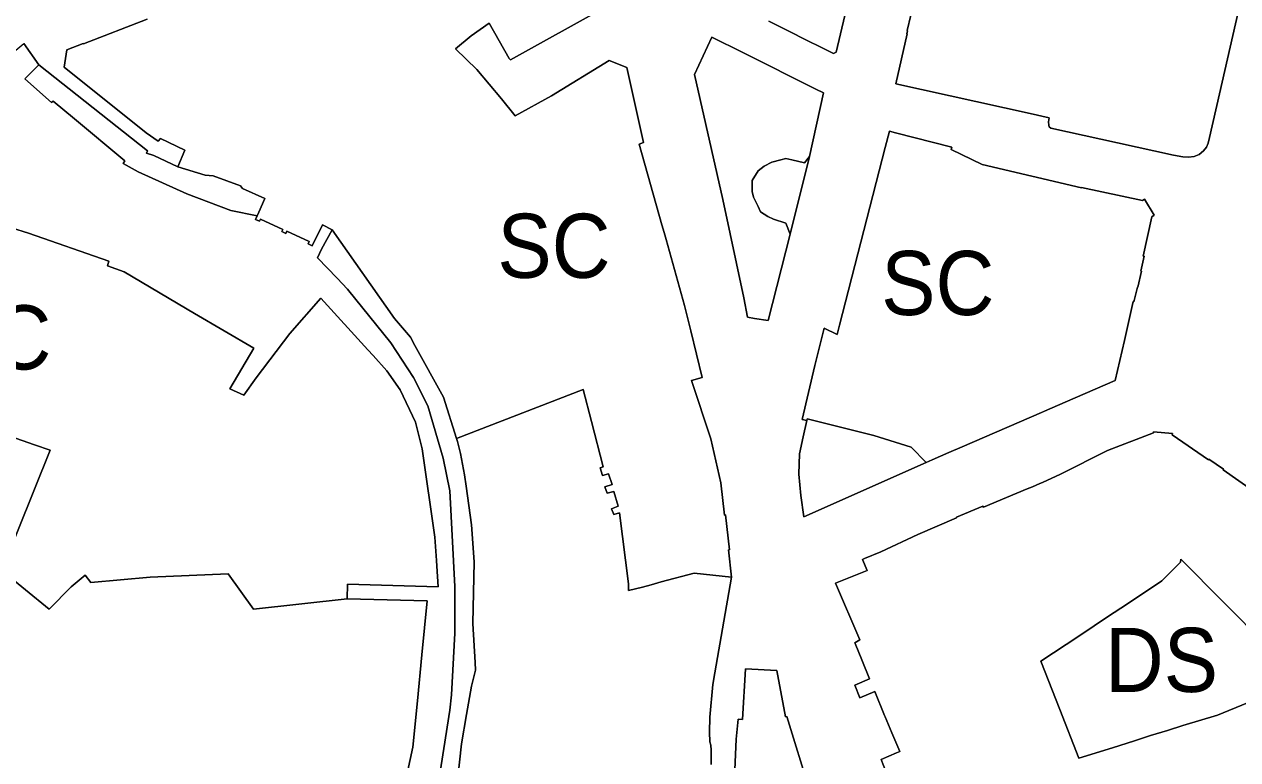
# Model space of a CAD drawing. Extents: x -650451 to -642268, y -1075216 to -1066610.
# Drawn here: x -647095.1 to -646868, y -1070849.7 to -1070712 of the extents above; entities that cross this region are included whole.
import ezdxf

# ---------------------------------------------------------------- set-up
doc = ezdxf.new("R2010")
doc.units = 0
doc.header["$LTSCALE"] = 4.8
for name, color, linetype, lineweight in [('1', 7, 'Continuous', 13), ('11', 7, 'Continuous', 13), ('15', 7, 'Continuous', 13), ('17', 7, 'Continuous', 13), ('2', 7, 'Continuous', 13), ('24', 7, 'Continuous', 13), ('40', 7, 'Continuous', 13), ('45', 7, 'Continuous', 13)]:
    doc.layers.add(name, color=color, linetype=linetype, lineweight=lineweight)
doc.layers.add('62', color=7, linetype='Continuous')

msp = doc.modelspace()

# ---------------------------------------------------------------- linework, layer by layer
at = {"layer": '1'}
msp.add_lwpolyline([(-646933.37, -1070853.01), (-646934.73, -1070849.64), (-646931.81, -1070848.41), (-646931.22, -1070848.17), (-646932.72, -1070844.62), (-646933.96, -1070841.66), (-646934.02, -1070841.52), (-646934.07, -1070841.39), (-646935.9, -1070836.93), (-646938.71, -1070838.08), (-646939.64, -1070835.71), (-646936.86, -1070834.57), (-646938.33, -1070831), (-646939.58, -1070827.93), (-646939.64, -1070827.79), (-646938.71, -1070827.23), (-646943.25, -1070816.65), (-646937.34, -1070814.25), (-646938.18, -1070812.2), (-646937.8, -1070812.01), (-646934.79, -1070810.78), (-646927.81, -1070807.55), (-646920.6, -1070804.42), (-646920.63, -1070804.31), (-646915.65, -1070802.21), (-646915.57, -1070802.42), (-646911.24, -1070800.61), (-646907.38, -1070798.99), (-646906.41, -1070798.59), (-646904.98, -1070797.99), (-646904.51, -1070797.79), (-646901.12, -1070796.23), (-646892.37, -1070791.83), (-646883.74, -1070788.5), (-646883.73, -1070788.3), (-646880.19, -1070788.64), (-646880.23, -1070788.85), (-646873.47, -1070793.54), (-646873.38, -1070793.42), (-646870.63, -1070795.33), (-646870.72, -1070795.45), (-646864.19, -1070799.98)], dxfattribs=at)
msp.add_lwpolyline([(-646878.61, -1070812.14), (-646878.66, -1070812.72), (-646882.18, -1070816.21), (-646887.3, -1070819.61), (-646889.85, -1070821.3), (-646892.34, -1070822.96), (-646897.34, -1070826.28), (-646900.09, -1070828.1), (-646904.8, -1070831.23), (-646901.26, -1070840.31), (-646897.71, -1070849.39), (-646891.42, -1070847.44), (-646887.32, -1070846.14), (-646884.27, -1070845.17), (-646881.11, -1070844.21), (-646878.26, -1070843.29), (-646871.78, -1070841.33), (-646860.55, -1070836.71), (-646856.41, -1070834.13), (-646862.56, -1070828.29)], close=True, dxfattribs=at)
at = {"layer": '11'}
for points in [[(-646935.85, -1070686.31), (-646943.1, -1070717.25), (-646943.61, -1070717.52), (-646945, -1070716.82), (-646949.56, -1070714.54), (-646951.12, -1070713.75), (-646955.71, -1070711.45)], [(-647127.36, -1070780.55), (-647112.25, -1070785.78), (-647100.16, -1070788.3), (-647093.12, -1070790.76), (-647090.24, -1070791.73), (-647099.26, -1070814.25)]]:
    msp.add_lwpolyline(points, dxfattribs=at)
msp.add_lwpolyline([(-646951.73, -1070751.34), (-646952.54, -1070749.28), (-646954.87, -1070748.5), (-646955.91, -1070747.98), (-646957.27, -1070747.14), (-646957.74, -1070746.13), (-646958.58, -1070744.41), (-646958.82, -1070743.34), (-646958.83, -1070741.26), (-646957.75, -1070739.44), (-646956.58, -1070738.61), (-646955.14, -1070737.86), (-646953.5, -1070737.42), (-646952.53, -1070737.15), (-646951.45, -1070737.4), (-646949.04, -1070737.98), (-646948.12, -1070736.75)], close=True, dxfattribs=at)
at = {"layer": '15'}
msp.add_line((-646951.73, -1070751.34), (-646948.12, -1070736.75), dxfattribs=at)
for points in [[(-646955.71, -1070711.45), (-646951.12, -1070713.75), (-646949.56, -1070714.54), (-646945, -1070716.82), (-646943.61, -1070717.52), (-646943.1, -1070717.25), (-646935.85, -1070686.31)], [(-646929.18, -1070710.3), (-646929.85, -1070713.22), (-646929.76, -1070713.24), (-646929.89, -1070713.79), (-646929.81, -1070713.81), (-646931.96, -1070723.16), (-646906.84, -1070728.72), (-646903.24, -1070729.57), (-646903.4, -1070730.32), (-646903.35, -1070730.9), (-646903.24, -1070731.23), (-646902.96, -1070731.45), (-646890.48, -1070734.21), (-646880.01, -1070736.53), (-646878.25, -1070736.85), (-646877.21, -1070736.9), (-646876.15, -1070736.76), (-646875.17, -1070736.39), (-646874.38, -1070735.72), (-646873.8, -1070735.04), (-646873.49, -1070734.28), (-646873.25, -1070733.21), (-646871.4, -1070725.07), (-646865.92, -1070700.98)], [(-646962.68, -1070815.49), (-646963.26, -1070810.4), (-646963.1, -1070810.38), (-646963.84, -1070803.87), (-646963.99, -1070803.89), (-646964.71, -1070797.83), (-646966.6, -1070789.62), (-646970.21, -1070778.7), (-646968.19, -1070778.16), (-646970.32, -1070769.4), (-646971.48, -1070764.65), (-646974.94, -1070752.34), (-646975.32, -1070751.02), (-646975.74, -1070749.55), (-646980.02, -1070734.49), (-646979.18, -1070734.14), (-646982.32, -1070720.12), (-646985.62, -1070718.8), (-646996.42, -1070725.42), (-647003.21, -1070729.14), (-647005.76, -1070725.98), (-647010.36, -1070720.51), (-647014.36, -1070716.64), (-647011.4, -1070714.21), (-647008.07, -1070711.83), (-647004.34, -1070718.44), (-647004.1, -1070718.67), (-646985.98, -1070708.66)], [(-647072.09, -1070711.08), (-647084.01, -1070715.68), (-647084.02, -1070715.63), (-647087.09, -1070716.82), (-647087.57, -1070720.08), (-647072.24, -1070732.33), (-647069.98, -1070733.93), (-647069.6, -1070733.43), (-647065.03, -1070735.57), (-647066.34, -1070738.73)], [(-646948.12, -1070736.75), (-646945.51, -1070724.86), (-646946.94, -1070724.15), (-646948.32, -1070723.46), (-646952.89, -1070721.18), (-646954.46, -1070720.4), (-646960.62, -1070717.32), (-646966.41, -1070714.43), (-646969.61, -1070721.45), (-646964.33, -1070744.8), (-646960.41, -1070763.23), (-646959.73, -1070766.88), (-646958.42, -1070767.08), (-646955.83, -1070767.49), (-646951.73, -1070751.34)], [(-647099.98, -1070715.28), (-647098.12, -1070718.12), (-647095.14, -1070715.62), (-647092.33, -1070719.64)], [(-647066.34, -1070738.73), (-647070.79, -1070736.62), (-647072.18, -1070736.18), (-647071.99, -1070735.71), (-647092.33, -1070719.64), (-647095.14, -1070715.62)], [(-647092.33, -1070719.64), (-647094.99, -1070722.25), (-647089.94, -1070726.7), (-647089.63, -1070726.41), (-647085.69, -1070729.7), (-647076.27, -1070737.56), (-647076.58, -1070738.1), (-647073.76, -1070739.62), (-647064.65, -1070743.79), (-647056.4, -1070746.9), (-647051.47, -1070747.87)], [(-646926.29, -1070794.08), (-646925.14, -1070793.57), (-646922.03, -1070792.21), (-646919.55, -1070791.13), (-646904.69, -1070784.68), (-646904.14, -1070784.44), (-646900.24, -1070782.75), (-646890.91, -1070778.69), (-646889.19, -1070771.22), (-646887.53, -1070763.95), (-646887.39, -1070763.96), (-646886.76, -1070761.25), (-646886.64, -1070761.25), (-646885.96, -1070758.23), (-646886.1, -1070758.22), (-646885.5, -1070755.44), (-646885.65, -1070755.43), (-646884.03, -1070748.05), (-646883.59, -1070747.76), (-646885.4, -1070744.75), (-646885.82, -1070744.99), (-646897.21, -1070742.56), (-646897.22, -1070742.62), (-646915.78, -1070738.26), (-646921.6, -1070735.48), (-646921.48, -1070735.03), (-646932, -1070732.32), (-646933.16, -1070732.02), (-646933.96, -1070735.12), (-646942.5, -1070768.36), (-646942.95, -1070770.09), (-646945.36, -1070768.9), (-646947.09, -1070775.88), (-646949.48, -1070785.99), (-646948.64, -1070786.2)], [(-647051.47, -1070747.87), (-647051.77, -1070748.55), (-647051.06, -1070748.88), (-647050.87, -1070748.48), (-647046.68, -1070750.42), (-647046.87, -1070750.83), (-647046.12, -1070751.18), (-647045.93, -1070750.77), (-647041.73, -1070752.72), (-647041.92, -1070753.13), (-647041.16, -1070753.49), (-647039.26, -1070749.59), (-647037.47, -1070750.49)], [(-647034.61, -1070819.54), (-647034.58, -1070816.84), (-647017.62, -1070817.34), (-647017.85, -1070813.46), (-647017.91, -1070812.41), (-647018.2, -1070808.02), (-647020.59, -1070791.49), (-647021.84, -1070786.49), (-647024.74, -1070780.46), (-647027.19, -1070776.89), (-647029.79, -1070774.04), (-647030.78, -1070772.96), (-647039.58, -1070763.3), (-647045.34, -1070769.89), (-647051.64, -1070778.2), (-647053.99, -1070781.45), (-647056.58, -1070780.29), (-647052.1, -1070772.65), (-647063.21, -1070766.15), (-647076.36, -1070758.34), (-647079.52, -1070757.22), (-647079.23, -1070756.36), (-647094.28, -1070751.13), (-647100.71, -1070749.14)], [(-647037.47, -1070750.49), (-647039.47, -1070754.14), (-647039.84, -1070754.92), (-647040.16, -1070755.74), (-647036.53, -1070759.54), (-647034.6, -1070761.61), (-647026.48, -1070771.66), (-647022.25, -1070778.15), (-647019.56, -1070783.47), (-647016.65, -1070793.24), (-647015.43, -1070799.33), (-647014.49, -1070817.24), (-647014.48, -1070825.99), (-647015.09, -1070837.53), (-647015.44, -1070840.42), (-647019.93, -1070869.12), (-647021.12, -1070882.75), (-647021.458, -1070891.298), (-647021.538, -1070893.318)], [(-646948.64, -1070786.2), (-646949.3, -1070789.28), (-646949.97, -1070792.46), (-646950.1, -1070796.26), (-646949.73, -1070800.24), (-646949.18, -1070804.22), (-646926.29, -1070794.08)], [(-646864.19, -1070799.98), (-646870.72, -1070795.45), (-646870.63, -1070795.33), (-646873.38, -1070793.42), (-646873.47, -1070793.54), (-646880.23, -1070788.85), (-646880.19, -1070788.64), (-646883.73, -1070788.3), (-646883.74, -1070788.5), (-646892.37, -1070791.83), (-646901.12, -1070796.23), (-646904.51, -1070797.79), (-646904.98, -1070797.99), (-646906.41, -1070798.59), (-646907.38, -1070798.99), (-646911.24, -1070800.61), (-646915.57, -1070802.42), (-646915.65, -1070802.21), (-646920.63, -1070804.31), (-646920.6, -1070804.42), (-646927.81, -1070807.55), (-646934.79, -1070810.78), (-646937.8, -1070812.01), (-646938.18, -1070812.2), (-646937.34, -1070814.25), (-646943.25, -1070816.65), (-646938.71, -1070827.23), (-646939.64, -1070827.79), (-646939.58, -1070827.93), (-646938.33, -1070831), (-646936.86, -1070834.57), (-646939.64, -1070835.71), (-646938.71, -1070838.08), (-646935.9, -1070836.93), (-646934.07, -1070841.39), (-646934.02, -1070841.52), (-646933.96, -1070841.66), (-646932.72, -1070844.62), (-646931.22, -1070848.17), (-646931.81, -1070848.41), (-646934.73, -1070849.64), (-646933.37, -1070853.01)], [(-646966.5, -1070850.6), (-646966.54, -1070847.91), (-646966.59, -1070846.94), (-646966.78, -1070846.31), (-646966.82, -1070844.53), (-646966.77, -1070841.69), (-646966.22, -1070835.58), (-646965.82, -1070833.4), (-646962.68, -1070815.49)], [(-647024.94, -1070859.43), (-647022.34, -1070847.31), (-647021.49, -1070838.65), (-647020.65, -1070830.04), (-647019.67, -1070819.93), (-647034.61, -1070819.54)], [(-646948.05, -1070855.57), (-646952.34, -1070841.59), (-646952.63, -1070841.63), (-646954.22, -1070832.97), (-646960.12, -1070832.69), (-646960.63, -1070842.14), (-646961.46, -1070842.07), (-646961.83, -1070845.86), (-646962.19, -1070854.43)]]:
    msp.add_lwpolyline(points, dxfattribs=at)
at = {"layer": '17'}
for points in [[(-646865.92, -1070700.98), (-646871.4, -1070725.07), (-646873.25, -1070733.21), (-646873.49, -1070734.28), (-646873.8, -1070735.04), (-646874.38, -1070735.72), (-646875.17, -1070736.39), (-646876.15, -1070736.76), (-646877.21, -1070736.9), (-646878.25, -1070736.85), (-646880.01, -1070736.53), (-646890.48, -1070734.21), (-646902.96, -1070731.45), (-646903.24, -1070731.23), (-646903.35, -1070730.9), (-646903.4, -1070730.32), (-646903.24, -1070729.57), (-646906.84, -1070728.72), (-646931.96, -1070723.16), (-646929.81, -1070713.81), (-646929.89, -1070713.79), (-646929.76, -1070713.24), (-646929.85, -1070713.22), (-646929.18, -1070710.3)], [(-646985.98, -1070708.66), (-647004.1, -1070718.67), (-647004.34, -1070718.44), (-647008.07, -1070711.83), (-647011.4, -1070714.21), (-647014.36, -1070716.64), (-647010.36, -1070720.51), (-647005.76, -1070725.98), (-647003.21, -1070729.14), (-646996.42, -1070725.42), (-646985.62, -1070718.8), (-646982.32, -1070720.12), (-646979.18, -1070734.14), (-646980.02, -1070734.49), (-646975.74, -1070749.55), (-646975.32, -1070751.02), (-646974.94, -1070752.34), (-646971.48, -1070764.65), (-646970.32, -1070769.4), (-646968.19, -1070778.16), (-646970.21, -1070778.7), (-646966.6, -1070789.62), (-646964.71, -1070797.83), (-646963.99, -1070803.89), (-646963.84, -1070803.87), (-646963.1, -1070810.38), (-646963.26, -1070810.4), (-646962.68, -1070815.49)], [(-647066.34, -1070738.73), (-647065.03, -1070735.57), (-647069.6, -1070733.43), (-647069.98, -1070733.93), (-647072.24, -1070732.33), (-647087.57, -1070720.08), (-647087.09, -1070716.82), (-647084.02, -1070715.63), (-647084.01, -1070715.68), (-647072.09, -1070711.08)], [(-646948.64, -1070786.2), (-646949.48, -1070785.99), (-646947.09, -1070775.88), (-646945.36, -1070768.9), (-646942.95, -1070770.09), (-646942.5, -1070768.36), (-646933.96, -1070735.12), (-646933.16, -1070732.02), (-646932, -1070732.32), (-646921.48, -1070735.03), (-646921.6, -1070735.48), (-646915.78, -1070738.26), (-646897.22, -1070742.62), (-646897.21, -1070742.56), (-646885.82, -1070744.99), (-646885.4, -1070744.75), (-646883.59, -1070747.76), (-646884.03, -1070748.05), (-646885.65, -1070755.43), (-646885.5, -1070755.44), (-646886.1, -1070758.22), (-646885.96, -1070758.23), (-646886.64, -1070761.25), (-646886.76, -1070761.25), (-646887.39, -1070763.96), (-646887.53, -1070763.95), (-646889.19, -1070771.22), (-646890.91, -1070778.69), (-646900.24, -1070782.75), (-646904.14, -1070784.44), (-646904.69, -1070784.68), (-646919.55, -1070791.13), (-646922.03, -1070792.21), (-646925.14, -1070793.57), (-646926.29, -1070794.08)], [(-647051.47, -1070747.87), (-647051.19, -1070747.22), (-647050.06, -1070744.63), (-647054.24, -1070742.75), (-647054.57, -1070742.28), (-647059.7, -1070740.42), (-647061.2, -1070740.26), (-647066.34, -1070738.73)], [(-647037.47, -1070750.49), (-647039.26, -1070749.59), (-647041.16, -1070753.49), (-647041.92, -1070753.13), (-647041.73, -1070752.72), (-647045.93, -1070750.77), (-647046.12, -1070751.18), (-647046.87, -1070750.83), (-647046.68, -1070750.42), (-647050.87, -1070748.48), (-647051.06, -1070748.88), (-647051.77, -1070748.55), (-647051.47, -1070747.87)], [(-647100.71, -1070749.14), (-647094.28, -1070751.13), (-647079.23, -1070756.36), (-647079.52, -1070757.22), (-647076.36, -1070758.34), (-647063.21, -1070766.15), (-647052.1, -1070772.65), (-647056.58, -1070780.29), (-647053.99, -1070781.45), (-647051.64, -1070778.2), (-647045.34, -1070769.89), (-647039.58, -1070763.3), (-647030.78, -1070772.96), (-647029.79, -1070774.04), (-647027.19, -1070776.89), (-647024.74, -1070780.46), (-647021.84, -1070786.49), (-647020.59, -1070791.49), (-647018.2, -1070808.02), (-647017.91, -1070812.41), (-647017.85, -1070813.46), (-647017.62, -1070817.34), (-647034.58, -1070816.84), (-647034.61, -1070819.54)], [(-647014.17, -1070789.53), (-647016.59, -1070781.8), (-647021.95, -1070772.16), (-647022.81, -1070770.62), (-647025.79, -1070767.12), (-647037.47, -1070750.49)], [(-647099.26, -1070814.25), (-647090.24, -1070791.73), (-647093.12, -1070790.76), (-647100.16, -1070788.3), (-647112.25, -1070785.78), (-647127.36, -1070780.55)], [(-646962.68, -1070815.49), (-646969.72, -1070814.79), (-646975.86, -1070816.38), (-646977.76, -1070816.93), (-646979.37, -1070817.4), (-646981.97, -1070818.04), (-646981.97, -1070816.79), (-646983.68, -1070803.47), (-646984.76, -1070803.79), (-646985.16, -1070802.75), (-646983.95, -1070802.22), (-646984.72, -1070799.46), (-646985.97, -1070799.81), (-646986.4, -1070798.61), (-646985.07, -1070798.18), (-646985.73, -1070796.18), (-646986.88, -1070796.5), (-646987.28, -1070795.05), (-646986.7, -1070794.86), (-646988.91, -1070786.4), (-646990.47, -1070780.4), (-647014.17, -1070789.53)], [(-646926.29, -1070794.08), (-646929.07, -1070791.17), (-646936.1, -1070788.99), (-646938.33, -1070788.42), (-646948.55, -1070785.86), (-646948.64, -1070786.2)], [(-647034.61, -1070819.54), (-647052.19, -1070821.53), (-647056.92, -1070814.86), (-647071.51, -1070815.52), (-647082.58, -1070816.51), (-647083.69, -1070815.12), (-647086.31, -1070817.34), (-647090.38, -1070821.49), (-647099.26, -1070814.25)]]:
    msp.add_lwpolyline(points, dxfattribs=at)
at = {"layer": '2'}
for points in [[(-647014.17, -1070789.53), (-646990.47, -1070780.4), (-646988.91, -1070786.4), (-646986.7, -1070794.86), (-646987.28, -1070795.05), (-646986.88, -1070796.5), (-646985.73, -1070796.18), (-646985.07, -1070798.18), (-646986.4, -1070798.61), (-646985.97, -1070799.81), (-646984.72, -1070799.46), (-646983.95, -1070802.22), (-646985.16, -1070802.75), (-646984.76, -1070803.79), (-646983.68, -1070803.47), (-646981.97, -1070816.79), (-646981.97, -1070818.04), (-646979.37, -1070817.4), (-646977.76, -1070816.93), (-646975.86, -1070816.38), (-646969.72, -1070814.79), (-646962.68, -1070815.49)], [(-647017.4, -1070890.8), (-647018.3, -1070880.69), (-647015.68, -1070865.44), (-647014.63, -1070858.82), (-647014.43, -1070857.54), (-647013.26, -1070846.7), (-647012.31, -1070841.21), (-647011.39, -1070835.93), (-647010.59, -1070832.94), (-647010.68, -1070831.5), (-647011.11, -1070824.16), (-647010.89, -1070812.67), (-647011.38, -1070805.72), (-647012.34, -1070798.51), (-647012.66, -1070796.33), (-647013.41, -1070792.39), (-647013.97, -1070790.15), (-647014.17, -1070789.53)], [(-647099.26, -1070814.25), (-647090.38, -1070821.49), (-647086.31, -1070817.34), (-647083.69, -1070815.12), (-647082.58, -1070816.51), (-647071.51, -1070815.52), (-647056.92, -1070814.86), (-647052.19, -1070821.53), (-647034.61, -1070819.54)], [(-646962.68, -1070815.49), (-646965.82, -1070833.4), (-646966.22, -1070835.58), (-646966.77, -1070841.69), (-646966.82, -1070844.53), (-646966.78, -1070846.31), (-646966.59, -1070846.94), (-646966.54, -1070847.91), (-646966.5, -1070850.6)], [(-647034.61, -1070819.54), (-647019.67, -1070819.93), (-647020.65, -1070830.04), (-647021.49, -1070838.65), (-647022.34, -1070847.31), (-647024.94, -1070859.43)], [(-646962.19, -1070854.43), (-646961.83, -1070845.86), (-646961.46, -1070842.07), (-646960.63, -1070842.14), (-646960.12, -1070832.69), (-646954.22, -1070832.97), (-646952.63, -1070841.63), (-646952.34, -1070841.59), (-646948.05, -1070855.57)]]:
    msp.add_lwpolyline(points, dxfattribs=at)
at = {"layer": '24'}
msp.add_lwpolyline([(-646878.61, -1070812.14), (-646862.56, -1070828.29), (-646856.41, -1070834.13), (-646860.55, -1070836.71), (-646871.78, -1070841.33), (-646878.26, -1070843.29), (-646881.11, -1070844.21), (-646884.27, -1070845.17), (-646887.32, -1070846.14), (-646891.42, -1070847.44), (-646897.71, -1070849.39), (-646901.26, -1070840.31), (-646904.8, -1070831.23), (-646900.09, -1070828.1), (-646897.34, -1070826.28), (-646892.34, -1070822.96), (-646889.85, -1070821.3), (-646887.3, -1070819.61), (-646882.18, -1070816.21), (-646878.66, -1070812.72)], close=True, dxfattribs=at)
at = {"layer": '40'}
for points in [[(-646951.73, -1070751.34), (-646955.83, -1070767.49), (-646958.42, -1070767.08), (-646959.73, -1070766.88), (-646960.41, -1070763.23), (-646964.33, -1070744.8), (-646969.61, -1070721.45), (-646966.41, -1070714.43), (-646960.62, -1070717.32), (-646954.46, -1070720.4), (-646952.89, -1070721.18), (-646948.32, -1070723.46), (-646946.94, -1070724.15), (-646945.51, -1070724.86), (-646948.12, -1070736.75)], [(-646948.12, -1070736.75), (-646949.04, -1070737.98), (-646951.45, -1070737.4), (-646952.53, -1070737.15), (-646953.5, -1070737.42), (-646955.14, -1070737.86), (-646956.58, -1070738.61), (-646957.75, -1070739.44), (-646958.83, -1070741.26), (-646958.82, -1070743.34), (-646958.58, -1070744.41), (-646957.74, -1070746.13), (-646957.27, -1070747.14), (-646955.91, -1070747.98), (-646954.87, -1070748.5), (-646952.54, -1070749.28), (-646951.73, -1070751.34)], [(-646926.29, -1070794.08), (-646949.18, -1070804.22), (-646949.73, -1070800.24), (-646950.1, -1070796.26), (-646949.97, -1070792.46), (-646949.3, -1070789.28), (-646948.64, -1070786.2)], [(-646948.64, -1070786.2), (-646948.55, -1070785.86), (-646938.33, -1070788.42), (-646936.1, -1070788.99), (-646929.07, -1070791.17), (-646926.29, -1070794.08)]]:
    msp.add_lwpolyline(points, dxfattribs=at)
at = {"layer": '45'}
for points in [[(-647051.47, -1070747.87), (-647056.4, -1070746.9), (-647064.65, -1070743.79), (-647073.76, -1070739.62), (-647076.58, -1070738.1), (-647076.27, -1070737.56), (-647085.69, -1070729.7), (-647089.63, -1070726.41), (-647089.94, -1070726.7), (-647094.99, -1070722.25), (-647092.33, -1070719.64)], [(-647092.33, -1070719.64), (-647071.99, -1070735.71), (-647072.18, -1070736.18), (-647070.79, -1070736.62), (-647066.34, -1070738.73)], [(-647066.34, -1070738.73), (-647061.2, -1070740.26), (-647059.7, -1070740.42), (-647054.57, -1070742.28), (-647054.24, -1070742.75), (-647050.06, -1070744.63), (-647051.19, -1070747.22), (-647051.47, -1070747.87)], [(-647021.458, -1070891.298), (-647021.12, -1070882.75), (-647019.93, -1070869.12), (-647015.44, -1070840.42), (-647015.09, -1070837.53), (-647014.48, -1070825.99), (-647014.49, -1070817.24), (-647015.43, -1070799.33), (-647016.65, -1070793.24), (-647019.56, -1070783.47), (-647022.25, -1070778.15), (-647026.48, -1070771.66), (-647034.6, -1070761.61), (-647036.53, -1070759.54), (-647040.16, -1070755.74), (-647039.84, -1070754.92), (-647039.47, -1070754.14), (-647037.47, -1070750.49)], [(-647037.47, -1070750.49), (-647025.79, -1070767.12), (-647022.81, -1070770.62), (-647021.95, -1070772.16), (-647016.59, -1070781.8), (-647014.17, -1070789.53)], [(-647014.17, -1070789.53), (-647013.97, -1070790.15), (-647013.41, -1070792.39), (-647012.66, -1070796.33), (-647012.34, -1070798.51), (-647011.38, -1070805.72), (-647010.89, -1070812.67), (-647011.11, -1070824.16), (-647010.68, -1070831.5), (-647010.59, -1070832.94), (-647011.39, -1070835.93), (-647012.31, -1070841.21), (-647013.26, -1070846.7), (-647014.43, -1070857.54), (-647014.63, -1070858.82), (-647015.68, -1070865.44), (-647018.3, -1070880.69), (-647017.4, -1070890.8), (-647021.458, -1070891.298)]]:
    msp.add_lwpolyline(points, dxfattribs=at)

# ---------------------------------------------------------------- texts
at = {"layer": '62', "width": 0.95}
for s, p in [('SC', (-647006.53, -1070759.491)), ('SC', (-646934.7, -1070766.455)), ('SC', (-647111.168, -1070776.636)), ('DS', (-646892.832, -1070836.999))]:
    msp.add_text(s, height=12, dxfattribs=at).set_placement(p)

doc.saveas('drawing.dxf')
